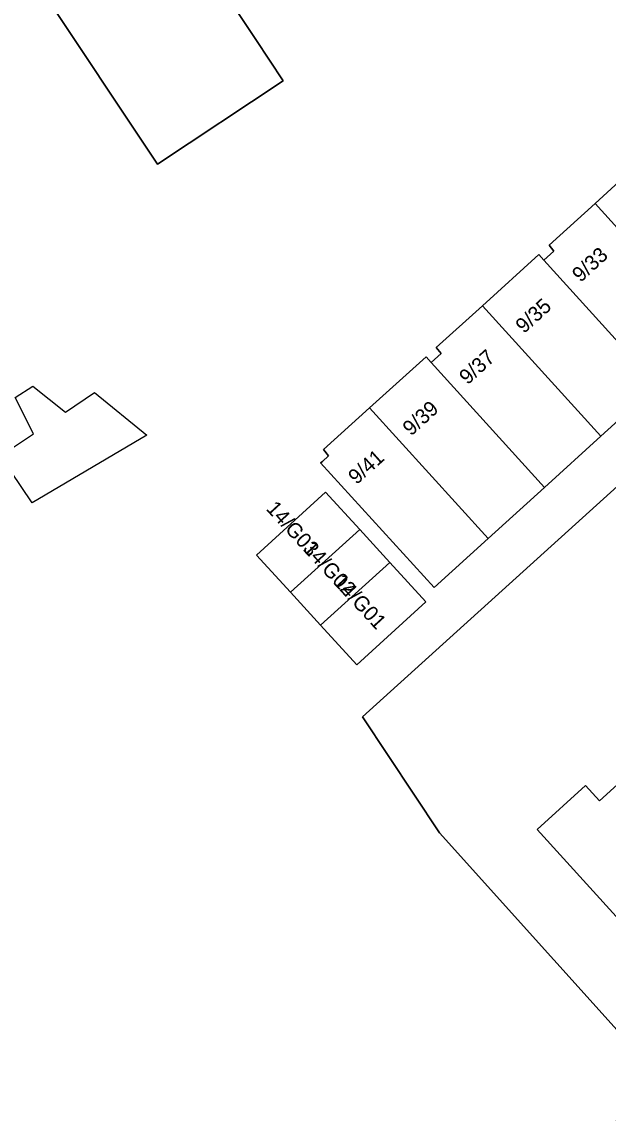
# Model space of a CAD drawing. Extents: x 161347 to 161881, y 382161 to 382804.
# Drawn here: x 161600.2 to 161639.5, y 382514.2 to 382587.4 of the extents above; entities that cross this region are included whole.
import ezdxf

# ---------------------------------------------------------------- set-up
doc = ezdxf.new("R2010")
doc.units = 0
for name, color, linetype in [('IMGEO_Erf', 7, 'Continuous'), ('IMGEO_Pand', 7, 'Continuous'), ('IMGEO_Pand_nummerreeks', 7, 'Continuous'), ('IMGEO_Pand_vergunning_verleend', 7, 'Continuous'), ('IMGEO_Parkeervlak_gesloten', 7, 'Continuous')]:
    doc.layers.add(name, color=color, linetype=linetype)

msp = doc.modelspace()

# ---------------------------------------------------------------- linework, layer by layer
at = {"layer": 'IMGEO_Erf'}
for points in [[(161572.092, 382591.77), (161539.981, 382570.178), (161537.341, 382557.85), (161565.95, 382511.235), (161572.292, 382501.343), (161572.851, 382501.493), (161573.727, 382500), (161581.489, 382486.772), (161593.113, 382483.942), (161618.484, 382500), (161639.588, 382513.357), (161643.126, 382515.61), (161643.533, 382515.936), (161628.206, 382532.98), (161623.055, 382540.753), (161664.71, 382578.468), (161661.6, 382581.894), (161665.593, 382585.519), (161669.295, 382588.879)], [(161613.931, 382589.146), (161615.901, 382586.187), (161617.744, 382583.418), (161609.323, 382577.814), (161601.467, 382589.619)], [(161642.81, 382563.004), (161639.033, 382559.573), (161635.261, 382556.146), (161631.484, 382552.714), (161627.867, 382549.428), (161620.25, 382557.788), (161620.362, 382557.891), (161620.777, 382558.269), (161620.449, 382558.695), (161623.528, 382561.479), (161627.315, 382564.903), (161627.66, 382564.521), (161628.322, 382565.125), (161627.995, 382565.522), (161631.087, 382568.329), (161634.865, 382571.758), (161635.209, 382571.379), (161635.886, 382571.983), (161635.557, 382572.386), (161638.636, 382575.188), (161642.407, 382578.62)]]:
    msp.add_lwpolyline(points, dxfattribs=at)
msp.add_lwpolyline([(161620.567, 382555.827), (161622.869, 382553.313), (161624.895, 382551.101), (161627.299, 382548.476), (161622.681, 382544.246), (161620.244, 382546.907), (161618.218, 382549.119), (161615.948, 382551.597)], close=True, dxfattribs=at)
at = {"layer": 'IMGEO_Pand'}
msp.add_lwpolyline([(161601.467, 382589.619), (161609.323, 382577.814), (161617.744, 382583.418), (161615.901, 382586.187), (161613.931, 382589.146)], dxfattribs=at)
for points in [[(161650.358, 382569.861), (161642.757, 382578.236), (161642.407, 382578.62), (161638.636, 382575.188), (161646.582, 382566.431)], [(161642.81, 382563.004), (161646.582, 382566.431), (161638.636, 382575.188), (161635.557, 382572.386), (161635.886, 382571.983), (161635.209, 382571.379)], [(161642.81, 382563.004), (161635.209, 382571.379), (161634.865, 382571.758), (161631.087, 382568.329), (161639.033, 382559.573)], [(161684.928, 382563.407), (161678.388, 382570.921), (161674.636, 382567.532), (161638.938, 382535.131), (161638.008, 382536.155), (161634.759, 382533.207), (161640.057, 382527.369), (161643.393, 382523.725), (161643.672, 382523.978), (161676.253, 382553.55), (161682.265, 382559.016), (161681.273, 382560.072), (161682.89, 382561.547)], [(161635.261, 382556.146), (161639.033, 382559.573), (161631.087, 382568.329), (161627.995, 382565.522), (161628.322, 382565.125), (161627.66, 382564.521)], [(161635.261, 382556.146), (161627.66, 382564.521), (161627.315, 382564.903), (161623.528, 382561.479), (161631.484, 382552.714)], [(161623.528, 382561.479), (161620.449, 382558.695), (161620.777, 382558.269), (161620.362, 382557.891), (161620.25, 382557.788), (161627.867, 382549.428), (161631.484, 382552.714)], [(161622.869, 382553.313), (161620.567, 382555.827), (161615.948, 382551.597), (161618.218, 382549.119)], [(161618.218, 382549.119), (161620.244, 382546.907), (161624.895, 382551.101), (161622.869, 382553.313)], [(161627.299, 382548.476), (161624.895, 382551.101), (161620.244, 382546.907), (161622.681, 382544.246)]]:
    msp.add_lwpolyline(points, close=True, dxfattribs=at)
at = {"layer": 'IMGEO_Pand_vergunning_verleend'}
msp.add_lwpolyline([(161598.788, 382558.262), (161601.01, 382559.736), (161599.78, 382562.167), (161600.967, 382562.944), (161603.149, 382561.186), (161605.103, 382562.508), (161608.602, 382559.648), (161600.908, 382555.108)], close=True, dxfattribs=at)
at = {"layer": 'IMGEO_Parkeervlak_gesloten'}
msp.add_lwpolyline([(161648.064, 382519.038), (161648.744, 382519.518), (161643.393, 382523.725), (161640.057, 382527.369), (161634.759, 382533.207), (161638.008, 382536.155), (161638.938, 382535.131), (161674.636, 382567.532), (161664.71, 382578.468), (161623.055, 382540.753), (161628.206, 382532.98), (161643.533, 382515.936), (161643.62, 382516.005)], close=True, dxfattribs=at)

# ---------------------------------------------------------------- texts
at = {"layer": 'IMGEO_Pand_nummerreeks'}
for s, rotation, p in [('9/33', 42.52529, (161637.665, 382569.851)), ('9/35', 42.26522, (161633.87, 382566.425)), ('9/37', 42.32675, (161630.095, 382562.986)), ('9/39', 42.17049, (161626.304, 382559.553)), ('9/41', 41.79265, (161622.649, 382556.29)), ('14/G03', 312.48461, (161616.544, 382554.678)), ('14/G02', 312.48423, (161619.011, 382551.984)), ('14/G01', 312.48461, (161621.038, 382549.772))]:
    msp.add_text(s, height=1, rotation=rotation, dxfattribs=at).set_placement(p)

doc.saveas('drawing.dxf')
